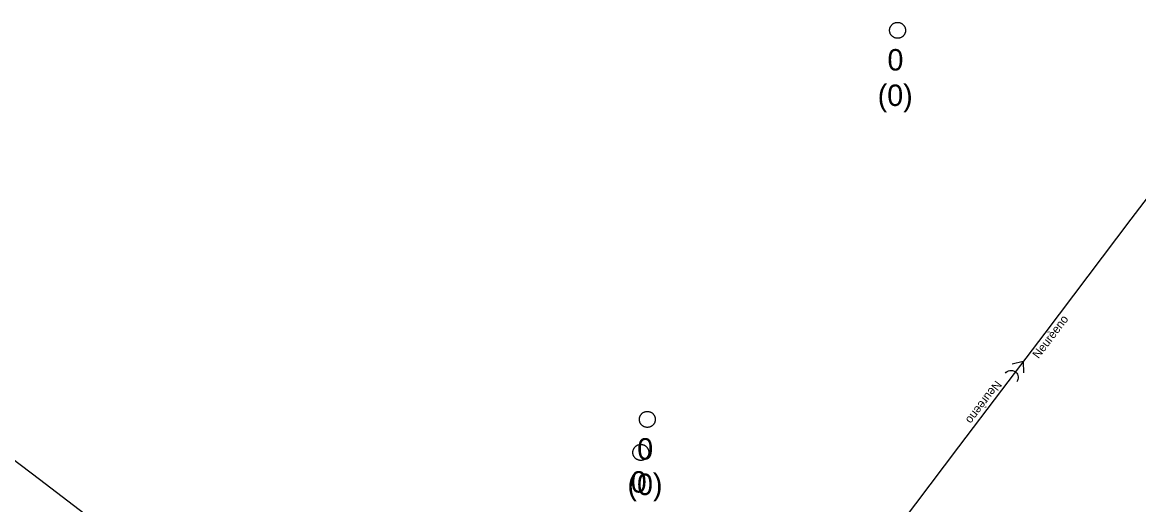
# Model space of a CAD drawing. Extents: x -606452 to -604459, y -1157823 to -1156972.
# Drawn here: x -605822.08 to -605787.1, y -1157507.67 to -1157492.57 of the extents above; entities that cross this region are included whole.
import ezdxf

# ---------------------------------------------------------------- set-up
doc = ezdxf.new("R2010")
doc.units = 0
doc.layers.add('Stoka', color=7, linetype='Continuous')
doc.layers.add('Vstupní šachta stoky', color=7, linetype='Continuous')

msp = doc.modelspace()

# ---------------------------------------------------------------- linework, layer by layer
at = {"layer": 'Stoka'}
for points in [[(-605785.992, -1157496.955), (-605787.343, -1157498.737)], [(-605787.343, -1157498.737), (-605788.694, -1157500.519)], [(-605788.694, -1157500.519), (-605790.046, -1157502.3)], [(-605790.046, -1157502.3), (-605791.397, -1157504.082)], [(-605790.722, -1157503.19), (-605791.061, -1157503.27)], [(-605790.721, -1157503.19), (-605790.705, -1157503.54)], [(-605791.278, -1157503.554), (-605791.25, -1157503.524), (-605791.217, -1157503.499), (-605791.18, -1157503.481), (-605791.141, -1157503.469), (-605791.099, -1157503.466), (-605791.058, -1157503.47), (-605791.019, -1157503.481), (-605790.982, -1157503.499), (-605790.949, -1157503.524), (-605790.921, -1157503.555), (-605790.9, -1157503.59), (-605790.885, -1157503.628), (-605790.877, -1157503.669), (-605790.877, -1157503.71), (-605790.885, -1157503.751), (-605790.9, -1157503.789), (-605790.922, -1157503.824)], [(-605791.397, -1157504.082), (-605792.748, -1157505.864)], [(-605821.548, -1157506.889), (-605823.332, -1157505.54)], [(-605792.748, -1157505.864), (-605794.099, -1157507.645)], [(-605819.765, -1157508.238), (-605821.548, -1157506.889)], [(-605794.099, -1157507.645), (-605795.45, -1157509.427)]]:
    msp.add_lwpolyline(points, dxfattribs=at)
at = {"layer": 'Vstupní šachta stoky'}
for p, q in [((-605794.669, -1157492.569), (-605794.656, -1157492.569)), ((-605802.51, -1157504.752), (-605802.497, -1157504.752)), ((-605802.714, -1157505.786), (-605802.701, -1157505.786))]:
    msp.add_line(p, q, dxfattribs=at)
for points in [[(-605794.656, -1157492.569), (-605794.643, -1157492.569), (-605794.63, -1157492.57), (-605794.617, -1157492.572), (-605794.604, -1157492.575), (-605794.591, -1157492.578), (-605794.578, -1157492.581), (-605794.566, -1157492.586), (-605794.554, -1157492.591), (-605794.542, -1157492.597), (-605794.53, -1157492.603), (-605794.519, -1157492.61), (-605794.508, -1157492.618), (-605794.498, -1157492.626), (-605794.488, -1157492.634), (-605794.478, -1157492.643), (-605794.469, -1157492.653), (-605794.461, -1157492.663), (-605794.453, -1157492.674), (-605794.445, -1157492.685), (-605794.438, -1157492.696), (-605794.432, -1157492.708), (-605794.427, -1157492.72), (-605794.422, -1157492.732), (-605794.417, -1157492.744), (-605794.414, -1157492.757), (-605794.411, -1157492.77), (-605794.409, -1157492.783), (-605794.407, -1157492.796), (-605794.406, -1157492.809), (-605794.406, -1157492.822), (-605794.407, -1157492.836), (-605794.408, -1157492.849), (-605794.41, -1157492.862), (-605794.412, -1157492.875), (-605794.416, -1157492.887), (-605794.419, -1157492.9), (-605794.424, -1157492.912), (-605794.429, -1157492.925), (-605794.435, -1157492.936), (-605794.442, -1157492.948), (-605794.449, -1157492.959), (-605794.456, -1157492.97), (-605794.465, -1157492.98), (-605794.473, -1157492.99), (-605794.483, -1157492.999), (-605794.493, -1157493.008), (-605794.503, -1157493.017), (-605794.513, -1157493.024), (-605794.524, -1157493.032), (-605794.536, -1157493.038), (-605794.548, -1157493.044), (-605794.56, -1157493.05), (-605794.572, -1157493.054), (-605794.584, -1157493.059), (-605794.597, -1157493.062), (-605794.61, -1157493.065), (-605794.623, -1157493.067), (-605794.636, -1157493.068), (-605794.649, -1157493.069), (-605794.663, -1157493.069), (-605794.676, -1157493.068), (-605794.689, -1157493.067), (-605794.702, -1157493.065), (-605794.715, -1157493.062), (-605794.728, -1157493.059), (-605794.74, -1157493.054), (-605794.752, -1157493.05), (-605794.764, -1157493.044), (-605794.776, -1157493.038), (-605794.788, -1157493.032), (-605794.799, -1157493.024), (-605794.809, -1157493.017), (-605794.819, -1157493.008), (-605794.829, -1157492.999), (-605794.839, -1157492.99), (-605794.847, -1157492.98), (-605794.856, -1157492.97), (-605794.863, -1157492.959), (-605794.87, -1157492.948), (-605794.877, -1157492.936), (-605794.883, -1157492.925), (-605794.888, -1157492.912), (-605794.893, -1157492.9), (-605794.896, -1157492.887), (-605794.9, -1157492.875), (-605794.902, -1157492.862), (-605794.904, -1157492.849), (-605794.905, -1157492.836), (-605794.906, -1157492.822), (-605794.906, -1157492.809), (-605794.905, -1157492.796), (-605794.903, -1157492.783), (-605794.901, -1157492.77), (-605794.898, -1157492.757), (-605794.895, -1157492.744), (-605794.89, -1157492.732), (-605794.885, -1157492.72), (-605794.88, -1157492.708), (-605794.874, -1157492.696), (-605794.867, -1157492.685)], [(-605794.867, -1157492.685), (-605794.859, -1157492.674), (-605794.851, -1157492.663), (-605794.843, -1157492.653), (-605794.834, -1157492.643), (-605794.824, -1157492.634), (-605794.814, -1157492.626), (-605794.804, -1157492.618), (-605794.793, -1157492.61), (-605794.782, -1157492.603), (-605794.77, -1157492.597), (-605794.758, -1157492.591), (-605794.746, -1157492.586), (-605794.734, -1157492.581), (-605794.721, -1157492.578), (-605794.708, -1157492.575), (-605794.695, -1157492.572), (-605794.682, -1157492.57), (-605794.669, -1157492.569)], [(-605802.497, -1157504.752), (-605802.484, -1157504.752), (-605802.471, -1157504.753), (-605802.458, -1157504.755), (-605802.445, -1157504.758), (-605802.432, -1157504.761), (-605802.419, -1157504.764), (-605802.407, -1157504.769), (-605802.395, -1157504.774), (-605802.383, -1157504.78), (-605802.371, -1157504.786), (-605802.36, -1157504.793), (-605802.349, -1157504.801), (-605802.339, -1157504.809), (-605802.329, -1157504.817), (-605802.319, -1157504.826), (-605802.31, -1157504.836), (-605802.302, -1157504.846), (-605802.294, -1157504.857), (-605802.286, -1157504.868), (-605802.279, -1157504.879), (-605802.273, -1157504.891), (-605802.268, -1157504.903), (-605802.263, -1157504.915), (-605802.258, -1157504.927), (-605802.255, -1157504.94), (-605802.252, -1157504.953), (-605802.25, -1157504.966), (-605802.248, -1157504.979), (-605802.247, -1157504.992), (-605802.247, -1157505.005), (-605802.248, -1157505.019), (-605802.249, -1157505.032), (-605802.251, -1157505.045), (-605802.253, -1157505.058), (-605802.257, -1157505.07), (-605802.26, -1157505.083), (-605802.265, -1157505.095), (-605802.27, -1157505.108), (-605802.276, -1157505.119), (-605802.283, -1157505.131), (-605802.29, -1157505.142), (-605802.297, -1157505.153), (-605802.306, -1157505.163), (-605802.314, -1157505.173), (-605802.324, -1157505.182), (-605802.334, -1157505.191), (-605802.344, -1157505.2), (-605802.354, -1157505.207), (-605802.365, -1157505.215), (-605802.377, -1157505.221), (-605802.389, -1157505.227), (-605802.401, -1157505.233), (-605802.413, -1157505.237), (-605802.425, -1157505.242), (-605802.438, -1157505.245), (-605802.451, -1157505.248), (-605802.464, -1157505.25), (-605802.477, -1157505.251), (-605802.49, -1157505.252), (-605802.504, -1157505.252), (-605802.517, -1157505.251), (-605802.53, -1157505.25), (-605802.543, -1157505.248), (-605802.556, -1157505.245), (-605802.569, -1157505.242), (-605802.581, -1157505.237), (-605802.593, -1157505.233), (-605802.605, -1157505.227), (-605802.617, -1157505.221), (-605802.629, -1157505.215), (-605802.64, -1157505.207), (-605802.65, -1157505.2), (-605802.66, -1157505.191), (-605802.67, -1157505.182), (-605802.68, -1157505.173), (-605802.688, -1157505.163), (-605802.697, -1157505.153), (-605802.704, -1157505.142), (-605802.711, -1157505.131), (-605802.718, -1157505.119), (-605802.724, -1157505.108), (-605802.729, -1157505.095), (-605802.734, -1157505.083), (-605802.737, -1157505.07), (-605802.741, -1157505.058), (-605802.743, -1157505.045), (-605802.745, -1157505.032), (-605802.746, -1157505.019), (-605802.747, -1157505.005), (-605802.747, -1157504.992), (-605802.746, -1157504.979), (-605802.744, -1157504.966), (-605802.742, -1157504.953), (-605802.739, -1157504.94), (-605802.736, -1157504.927), (-605802.731, -1157504.915), (-605802.726, -1157504.903), (-605802.721, -1157504.891), (-605802.715, -1157504.879), (-605802.708, -1157504.868)], [(-605802.708, -1157504.868), (-605802.7, -1157504.857), (-605802.692, -1157504.846), (-605802.684, -1157504.836), (-605802.675, -1157504.826), (-605802.665, -1157504.817), (-605802.655, -1157504.809), (-605802.645, -1157504.801), (-605802.634, -1157504.793), (-605802.623, -1157504.786), (-605802.611, -1157504.78), (-605802.599, -1157504.774), (-605802.587, -1157504.769), (-605802.575, -1157504.764), (-605802.562, -1157504.761), (-605802.549, -1157504.758), (-605802.536, -1157504.755), (-605802.523, -1157504.753), (-605802.51, -1157504.752)], [(-605802.701, -1157505.786), (-605802.688, -1157505.786), (-605802.675, -1157505.787), (-605802.662, -1157505.789), (-605802.649, -1157505.792), (-605802.636, -1157505.795), (-605802.623, -1157505.798), (-605802.611, -1157505.803), (-605802.599, -1157505.808), (-605802.587, -1157505.814), (-605802.575, -1157505.82), (-605802.564, -1157505.827), (-605802.553, -1157505.835), (-605802.543, -1157505.843), (-605802.533, -1157505.851), (-605802.523, -1157505.86), (-605802.514, -1157505.87), (-605802.506, -1157505.88), (-605802.498, -1157505.891), (-605802.49, -1157505.902), (-605802.483, -1157505.913), (-605802.477, -1157505.925), (-605802.472, -1157505.937), (-605802.467, -1157505.949), (-605802.462, -1157505.961), (-605802.459, -1157505.974), (-605802.456, -1157505.987), (-605802.454, -1157506), (-605802.452, -1157506.013), (-605802.451, -1157506.026), (-605802.451, -1157506.039), (-605802.452, -1157506.053), (-605802.453, -1157506.066), (-605802.455, -1157506.079), (-605802.457, -1157506.092), (-605802.461, -1157506.104), (-605802.464, -1157506.117), (-605802.469, -1157506.129), (-605802.474, -1157506.142), (-605802.48, -1157506.153), (-605802.487, -1157506.165), (-605802.494, -1157506.176), (-605802.501, -1157506.187), (-605802.51, -1157506.197), (-605802.518, -1157506.207), (-605802.528, -1157506.216), (-605802.538, -1157506.225), (-605802.548, -1157506.234), (-605802.558, -1157506.241), (-605802.569, -1157506.249), (-605802.581, -1157506.255), (-605802.593, -1157506.261), (-605802.605, -1157506.267), (-605802.617, -1157506.271), (-605802.629, -1157506.276), (-605802.642, -1157506.279), (-605802.655, -1157506.282), (-605802.668, -1157506.284), (-605802.681, -1157506.285), (-605802.694, -1157506.286), (-605802.708, -1157506.286), (-605802.721, -1157506.285), (-605802.734, -1157506.284), (-605802.747, -1157506.282), (-605802.76, -1157506.279), (-605802.773, -1157506.276), (-605802.785, -1157506.271), (-605802.797, -1157506.267), (-605802.809, -1157506.261), (-605802.821, -1157506.255), (-605802.833, -1157506.249), (-605802.844, -1157506.241), (-605802.854, -1157506.234), (-605802.864, -1157506.225), (-605802.874, -1157506.216), (-605802.884, -1157506.207), (-605802.892, -1157506.197), (-605802.901, -1157506.187), (-605802.908, -1157506.176), (-605802.915, -1157506.165), (-605802.922, -1157506.153), (-605802.928, -1157506.142), (-605802.933, -1157506.129), (-605802.938, -1157506.117), (-605802.941, -1157506.104), (-605802.945, -1157506.092), (-605802.947, -1157506.079), (-605802.949, -1157506.066), (-605802.95, -1157506.053), (-605802.951, -1157506.039), (-605802.951, -1157506.026), (-605802.95, -1157506.013), (-605802.948, -1157506), (-605802.946, -1157505.987), (-605802.943, -1157505.974), (-605802.94, -1157505.961), (-605802.935, -1157505.949), (-605802.93, -1157505.937), (-605802.925, -1157505.925), (-605802.919, -1157505.913), (-605802.912, -1157505.902)], [(-605802.912, -1157505.902), (-605802.904, -1157505.891), (-605802.896, -1157505.88), (-605802.888, -1157505.87), (-605802.879, -1157505.86), (-605802.869, -1157505.851), (-605802.859, -1157505.843), (-605802.849, -1157505.835), (-605802.838, -1157505.827), (-605802.827, -1157505.82), (-605802.815, -1157505.814), (-605802.803, -1157505.808), (-605802.791, -1157505.803), (-605802.779, -1157505.798), (-605802.766, -1157505.795), (-605802.753, -1157505.792), (-605802.74, -1157505.789), (-605802.727, -1157505.787), (-605802.714, -1157505.786)]]:
    msp.add_lwpolyline(points, dxfattribs=at)

# ---------------------------------------------------------------- texts
at = {"layer": 'Stoka'}
for rotation, p in [(52.8248, (-605790.24, -1157503.119)), (232.8248, (-605791.581, -1157503.763))]:
    msp.add_text('Neurèeno', height=0.2683, rotation=rotation, dxfattribs=at).set_placement(p)
at = {"layer": 'Vstupní šachta stoky'}
for s, height, p in [('0', 0.671, (-605794.972, -1157494.077)), ('(0)', 0.6708, (-605795.278, -1157495.188)), ('0', 0.671, (-605802.813, -1157506.26)), ('(0)', 0.6708, (-605803.119, -1157507.371)), ('0', 0.671, (-605803.017, -1157507.294))]:
    msp.add_text(s, height=height, dxfattribs=at).set_placement(p)

doc.saveas('drawing.dxf')
